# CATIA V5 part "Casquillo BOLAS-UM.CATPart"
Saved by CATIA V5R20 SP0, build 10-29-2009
Part number: Casquillo BOLAS-UM
Revision: ANY
Definition: UNKNOWN
Nomenclature: Casquillo BOLAS-UM
Source: Unknown
Bounding box of the stored display mesh (mm): x -1.775 to 1.775, y 0 to 5, z -1.775 to 1.775
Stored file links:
  C:\Users\Utente\Desktop\IO LAVORO\3D X SITO CF\X SITO\3D files UM\UM064242 PRODUCT\Casquillo BOLAS-UM.CATPart
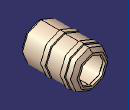
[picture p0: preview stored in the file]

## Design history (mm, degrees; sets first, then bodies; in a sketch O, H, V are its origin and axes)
Body1 "Chaflán3" (main body)
  Solid1: solid without history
